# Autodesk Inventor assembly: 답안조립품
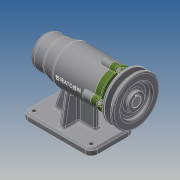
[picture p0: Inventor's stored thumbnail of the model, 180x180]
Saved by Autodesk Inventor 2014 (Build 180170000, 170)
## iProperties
Created: 2019-07
Part Number: 답안조립품
Document SubType Name: Assembly
Designer: kb542-18
Author: kb542-18
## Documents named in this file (12)
- C:\Users\kb542-18\Desktop\490704V1056\답안조립품.iam
- C:\Users\kb542-18\Desktop\490704V1056\본체.ipt
- C:\Users\kb542-18\Desktop\490704V1056\볼트 M4.ipt
- C:\Users\kb542-18\Desktop\490704V1056\어댑터슬리브.ipt
- C:\Users\kb542-18\Desktop\490704V1056\오일 실.ipt
- C:\Users\kb542-18\Desktop\490704V1056\축.ipt
- C:\Users\kb542-18\Desktop\490704V1056\커버.ipt
- C:\Users\kb542-18\Desktop\490704V1056\키 5 x 5 x 16.ipt
- C:\Users\kb542-18\Desktop\490704V1056\V벨트풀리.ipt
- C:\Users\kb542-18\Desktop\490704V1056\멈춤나사 M3.ipt
- C:\Users\kb542-18\Desktop\490704V1056\베어링 6004.ipt
- C:\Users\kb542-18\Desktop\490704V1056\베어링 51202.ipt
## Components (1 placed, 1 different names)
1. V벨트풀리:1
